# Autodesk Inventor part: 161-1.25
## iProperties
Created: 2007-06
Part Number: 161-1.25
Document SubType Name: Modeling
Designer: btaylor
Density: 1 g/cm^3
Author: btaylor
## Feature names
1. Extrusion1
2. Extrusion2
3. Extrusion3
4. Extrusion4
5. Extrusion5
6. Fillet1
7. Fillet2
8. Fillet3
9. Fillet4
10. Extrusion6
11. Extrusion7
12. Extrusion8
13. Chamfer1
14. Chamfer2
15. Chamfer3
16. Fillet5
17. Fillet6
18. Fillet7
19. Extrusion9
20. Extrusion10
21. Fillet9
22. Fillet10
23. Fillet11
24. Fillet12
